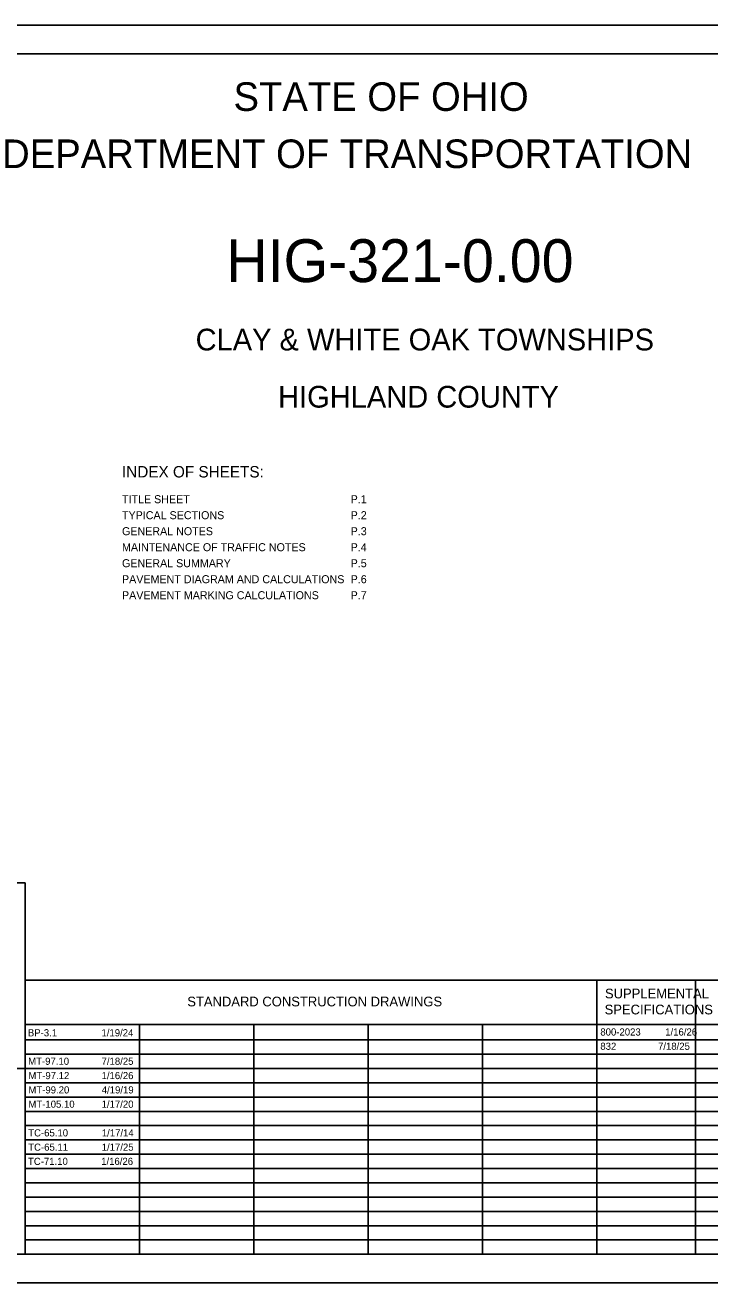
# Model space of a CAD drawing. Extents: x 0 to 34, y 0 to 22.
# Drawn here: x 10.15 to 22.13, y 0 to 22 of the extents above; entities that cross this region are included whole.
import ezdxf

# ---------------------------------------------------------------- set-up
doc = ezdxf.new("R2010")
doc.units = 0
for name, color, linetype in [('Default', 7, 'Continuous'), ('SH_Border', 7, 'Continuous'), ('SH_Cut_Line', 7, 'Continuous'), ('SH_Data', 7, 'Continuous'), ('SH_Text', 7, 'Continuous')]:
    doc.layers.add(name, color=color, linetype=linetype)

msp = doc.modelspace()

# ---------------------------------------------------------------- linework, layer by layer
at = {"layer": 'SH_Border'}
msp.add_lwpolyline([(1.5, 21.5), (33.5, 21.5), (33.5, 0.5), (1.5, 0.5)], close=True, dxfattribs=at)
at = {"layer": 'SH_Cut_Line'}
msp.add_lwpolyline([(0, 0), (34, 0), (34, 22), (0, 22)], close=True, dxfattribs=at)
at = {"layer": 'SH_Data'}
for p, q in [((10.15, 5.292), (23.6, 5.292)), ((10.15, 0.5), (10.15, 5.292)), ((20.15, 0.5), (20.15, 5.292)), ((21.875, 0.5), (21.875, 5.292)), ((10.15, 4.521), (23.6, 4.521)), ((12.15, 0.5), (12.15, 4.521)), ((14.15, 0.5), (14.15, 4.521)), ((16.15, 0.5), (16.15, 4.521)), ((18.15, 0.5), (18.15, 4.521)), ((10.15, 4.25), (23.6, 4.25)), ((10.15, 4), (23.6, 4)), ((10.15, 3.75), (23.6, 3.75)), ((10.15, 3.5), (23.6, 3.5)), ((10.15, 3.25), (23.6, 3.25)), ((10.15, 3), (23.6, 3)), ((10.15, 2.75), (23.6, 2.75)), ((10.15, 2.5), (23.6, 2.5)), ((10.15, 2.25), (23.6, 2.25)), ((10.15, 2), (23.6, 2)), ((10.15, 1.75), (23.6, 1.75)), ((10.15, 1.5), (23.6, 1.5)), ((10.15, 1.25), (23.6, 1.25)), ((10.15, 1), (23.6, 1)), ((10.15, 0.75), (23.6, 0.75))]:
    msp.add_line(p, q, dxfattribs=at)
for points in [[(10.15, 7), (7.35, 7), (7.35, 3.75), (10.15, 3.75)], [(10.15, 3.75), (7.35, 3.75), (7.35, 0.5), (10.15, 0.5)]]:
    msp.add_lwpolyline(points, close=True, dxfattribs=at)

# ---------------------------------------------------------------- texts
at = {"layer": 'Default'}
for s, p in [('BP-3.1', (10.198, 4.312)), ('1/19/24', (11.485, 4.312)), ('800-2023', (20.212, 4.326)), ('1/16/26', (21.347, 4.326)), ('832', (20.212, 4.076)), ('7/18/25', (21.221, 4.076)), ('MT-97.10', (10.203, 3.814)), ('7/18/25', (11.487, 3.814)), ('MT-97.12', (10.207, 3.563)), ('1/16/26', (11.487, 3.563)), ('MT-99.20', (10.207, 3.313)), ('4/19/19', (11.49, 3.313)), ('MT-105.10', (10.207, 3.063)), ('1/17/20', (11.488, 3.063)), ('TC-65.10', (10.204, 2.561)), ('1/17/14', (11.491, 2.561)), ('TC-65.11', (10.204, 2.311)), ('1/17/25', (11.489, 2.311)), ('TC-71.10', (10.2, 2.063)), ('1/16/26', (11.48, 2.063))]:
    msp.add_text(s, height=0.125, dxfattribs=at).set_placement(p)
at = {"layer": 'SH_Text'}
for s, height, p in [('STATE OF OHIO', 0.5, (13.795, 20.5)), ('DEPARTMENT OF TRANSPORTATION', 0.5, (9.747, 19.5)), ('HIG-321-0.00', 0.75, (13.667, 17.505)), ('CLAY & WHITE OAK TOWNSHIPS', 0.38, (13.132, 16.31)), ('HIGHLAND COUNTY', 0.38, (14.575, 15.31)), ('INDEX OF SHEETS:', 0.2, (11.844, 14.088)), ('TITLE SHEET', 0.14, (11.844, 13.638)), ('P.1', 0.14, (15.844, 13.638)), ('TYPICAL SECTIONS', 0.14, (11.844, 13.358)), ('P.2', 0.14, (15.844, 13.358)), ('GENERAL NOTES', 0.14, (11.844, 13.078)), ('P.3', 0.14, (15.844, 13.078)), ('MAINTENANCE OF TRAFFIC NOTES', 0.14, (11.844, 12.798)), ('P.4', 0.14, (15.844, 12.798)), ('GENERAL SUMMARY', 0.14, (11.844, 12.518)), ('P.5', 0.14, (15.844, 12.518)), ('PAVEMENT DIAGRAM AND CALCULATIONS', 0.14, (11.844, 12.238)), ('P.6', 0.14, (15.844, 12.238)), ('PAVEMENT MARKING CALCULATIONS', 0.14, (11.844, 11.958)), ('P.7', 0.14, (15.844, 11.958)), ('SUPPLEMENTAL', 0.17, (20.293, 4.976)), ('STANDARD CONSTRUCTION DRAWINGS', 0.17, (12.986, 4.836)), ('SPECIFICATIONS', 0.17, (20.287, 4.696))]:
    msp.add_text(s, height=height, dxfattribs=at).set_placement(p)

doc.saveas('drawing.dxf')
